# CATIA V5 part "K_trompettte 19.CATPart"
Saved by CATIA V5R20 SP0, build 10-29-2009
Part number: trompettte 19
Bounding box of the stored display mesh (mm): x -49.997 to 49.997, y -49.994 to 49.994, z 0 to 300
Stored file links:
  G:\Khaled_CFAO_2011\SIL\SIL_GR1\gperrin\Khaled\CAD_CATIA\Khaled\K_trompettte 19.CATPart
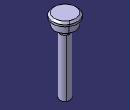
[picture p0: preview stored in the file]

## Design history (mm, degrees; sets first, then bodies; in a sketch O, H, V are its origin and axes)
Parameters
  Hauteur = 300
Set1
  Point1: type OnPlane, Support face of Shaft1 from Sketch1.L2, H 0, V 0, Direction (1, 0, 0)
Body1 (main body)
  Sketch1 on yz-plane, origin (0, 0, 0), H (0, 1, 0), V (0, 0, 1)
    axis line L1 (0, 87) -> (0, -103)
    point P1 (0, 87)
    line L2 (0, 300) -> (42.3865, 300)
    point P3 (0, 300)
    point P4 (50, 300)
    line L3 (50, 292.3865) -> (50, 285)
    line L4 (50, 285) -> (41, 285)
    line L5 (41, 285) -> (41, 255)
    point P7 (41, 255)
    line L6 (41, 255) -> (20, 234)
    line L7 (20, 234) -> (20, 0)
    point P9 (20, 0)
    line L8 (42.3865, 300) -> (50, 292.3865)
    line L9 (20, 0) -> (15, 0)
    line L10 (15, 0) -> (15, 252)
    line L11 (15, 252) -> (0, 252)
    point P14 (0, 252)
    line L12 (0, 252) -> (0, 300)
    distance L5 L1 = 41
    distance P3 P4 = 50
    angle L2 L8 = 45
    length L8 = 10.7671
    distance L7 L1 = 20
    distance H L2 = 300
    distance L4 L2 = 15
    distance L4 P7 = 30
    angle L6 L7 = 135
    distance L10 L1 = 15
    coincidence: P1 V, P3 L1, L2 P4, L3 P4, P9 H, P14 V
    vertical: L1 V, L3 V, L5 V, L7 V, L10 V, L12 V
    horizontal: L2 H, L4 H, L9 H, L11 H
  Shaft1: profile Sketch1, axis Sketch1.L1, angle 360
